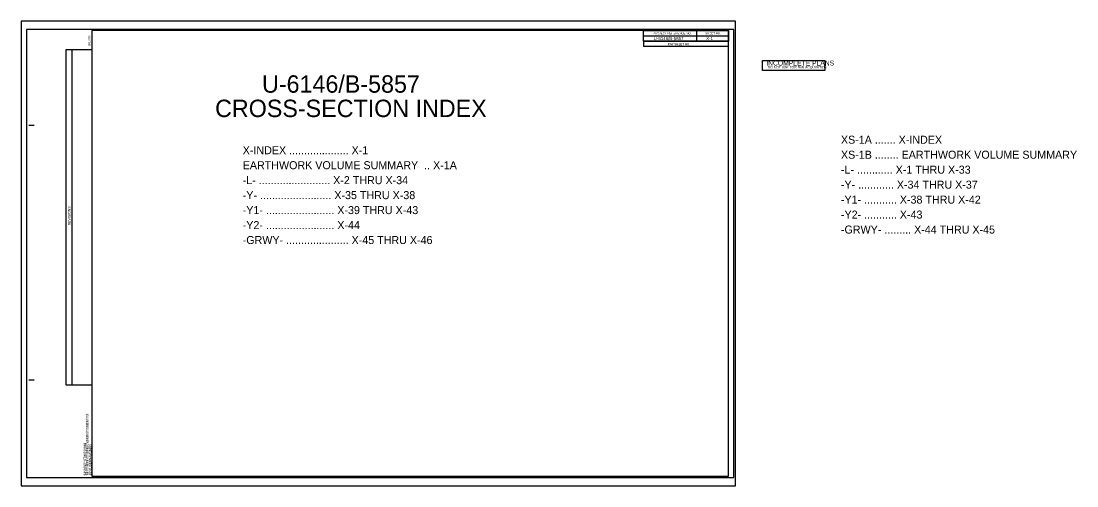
# Model space of a CAD drawing. Extents: x -5 to 493, y 254 to 473.
import ezdxf

# ---------------------------------------------------------------- set-up
doc = ezdxf.new("R2010")
doc.units = 0
for name, color, linetype in [('Prop DSN Text', 7, 'Continuous'), ('Sheet Block Revision CELL', 7, 'Continuous'), ('Sheet Cutting Line CELL', 7, 'Continuous'), ('Sheet Data Field CELL', 7, 'Continuous'), ('Sheet Plan CELL', 7, 'Continuous'), ('Sheet Plot Border Inside CELL', 7, 'Continuous'), ('Sheet Plot Border Outside CELL', 7, 'Continuous'), ('Sheet Sticker Incomplete CELL', 7, 'Continuous')]:
    doc.layers.add(name, color=color, linetype=linetype)

msp = doc.modelspace()

# ---------------------------------------------------------------- linework, layer by layer
at = {"layer": 'Sheet Block Revision CELL'}
msp.add_line((19.24, 301.35), (19.24, 459.48), dxfattribs=at)
msp.add_lwpolyline([(16.33, 301.35), (16.33, 459.48), (28.44, 459.48), (28.44, 301.35)], close=True, dxfattribs=at)
at = {"layer": 'Sheet Cutting Line CELL'}
for p, q in [((331.84, 472.85), (-4.86, 472.85)), ((-4.86, 472.85), (-4.86, 253.85)), ((-4.86, 253.85), (331.84, 253.85))]:
    msp.add_line(p, q, dxfattribs=at)
at = {"layer": 'Sheet Plan CELL'}
for p, q in [((28.44, 468.35), (28.44, 468.35)), ((313.43, 468.34), (313.44, 463.34)), ((288.43, 465.84), (328.44, 465.84)), ((288.43, 463.34), (328.44, 463.34)), ((288.43, 463.34), (288.43, 460.84)), ((288.43, 463.34), (328.44, 463.34)), ((328.44, 460.84), (288.43, 460.84)), ((-1.26, 423.85), (1.24, 423.85)), ((-1.26, 303.85), (1.24, 303.85)), ((28.44, 258.35), (28.44, 258.35))]:
    msp.add_line(p, q, dxfattribs=at)
for points in [[(328.45, 468.35), (28.44, 468.35), (28.44, 258.35), (328.44, 258.35)], [(288.43, 468.35), (328.45, 468.35), (328.44, 463.34), (288.43, 463.34)]]:
    msp.add_lwpolyline(points, close=True, dxfattribs=at)
at = {"layer": 'Sheet Plot Border Inside CELL'}
msp.add_lwpolyline([(-2.26, 257.85), (330.94, 257.85), (330.94, 468.85), (-2.26, 468.85)], close=True, dxfattribs=at)
at = {"layer": 'Sheet Plot Border Outside CELL'}
msp.add_lwpolyline([(-4.86, 253.85), (331.84, 253.85), (331.84, 472.85), (-4.86, 472.85)], close=True, dxfattribs=at)
at = {"layer": 'Sheet Sticker Incomplete CELL'}
msp.add_lwpolyline([(344.47, 449.59), (344.47, 454.29), (373.87, 454.29), (373.87, 449.59)], close=True, dxfattribs=at)

# ---------------------------------------------------------------- texts
at = {"layer": 'Prop DSN Text'}
for s, height, p in [('U-6146/B-5857', 8.2021, (108.66, 439.11)), ('CROSS-SECTION INDEX', 8.2021, (86.55, 427.63)), ('XS-1A ....... X-INDEX', 3.773, (381.45, 415.07)), ('X-INDEX .................... X-1', 3.773, (99.56, 410.12)), ('XS-1B ........ EARTHWORK VOLUME SUMMARY', 3.773, (381.45, 408.01)), ('EARTHWORK VOLUME SUMMARY  .. X-1A', 3.773, (99.56, 403.07)), ('-L- ............ X-1 THRU X-33', 3.773, (381.45, 400.96)), ('-L- ........................ X-2 THRU X-34', 3.773, (99.56, 396.02)), ('-Y- ............ X-34 THRU X-37', 3.773, (381.45, 393.91)), ('-Y- ........................ X-35 THRU X-38', 3.773, (99.56, 388.96)), ('-Y1- ........... X-38 THRU X-42', 3.773, (381.45, 386.85)), ('-Y1- ....................... X-39 THRU X-43', 3.773, (99.56, 381.91)), ('-Y2- ........... X-43', 3.773, (381.45, 379.8)), ('-Y2- ....................... X-44', 3.773, (99.56, 374.85)), ('-GRWY- ......... X-44 THRU X-45', 3.773, (381.45, 372.74)), ('-GRWY- ..................... X-45 THRU X-46', 3.773, (99.56, 367.8))]:
    msp.add_text(s, height=height, dxfattribs=at).set_placement(p)
at = {"layer": 'Sheet Block Revision CELL'}
msp.add_text('REVISIONS', height=1.2, rotation=90, dxfattribs=at).set_placement((18.43, 376.58))
at = {"layer": 'Sheet Data Field CELL'}
for s, p in [('U-6146/B-5857', (293.2, 463.89)), ('   X-1   ', (316.23, 463.9))]:
    msp.add_text(s, height=1.5, rotation=0, dxfattribs=at).set_placement(p)
at = {"layer": 'Sheet Plan CELL'}
for s, height, rotation, p in [('8/17/99', 1.05, 90, (27.79, 461.31)), ('PROJECT REFERENCE NO.', 1, 0, (292.87, 466.61)), ('SHEET NO.', 1, 0, (317.5, 466.59)), ('R/W SHEET NO.', 1, 0, (299.83, 461.5)), ('$$$$$$$$$$$$$$$$DGN$$$$$$$$$$$$$$$$', 1.05, 90, (26.91, 258.82)), ('$$$$$$SYSTIME$$$$$', 1.05, 90, (25.7, 258.82)), ('$$$$USERNAME$$$$', 1.05, 90, (28.22, 258.83))]:
    msp.add_text(s, height=height, rotation=rotation, dxfattribs=at).set_placement(p)
at = {"layer": 'Sheet Sticker Incomplete CELL'}
for s, height, p in [('INCOMPLETE PLANS', 2.304, (346.26, 451.93)), ('DO NOT USE FOR R/W ACQUISITION', 1.152, (346.91, 450.54))]:
    msp.add_text(s, height=height, dxfattribs=at).set_placement(p)

doc.saveas('drawing.dxf')
